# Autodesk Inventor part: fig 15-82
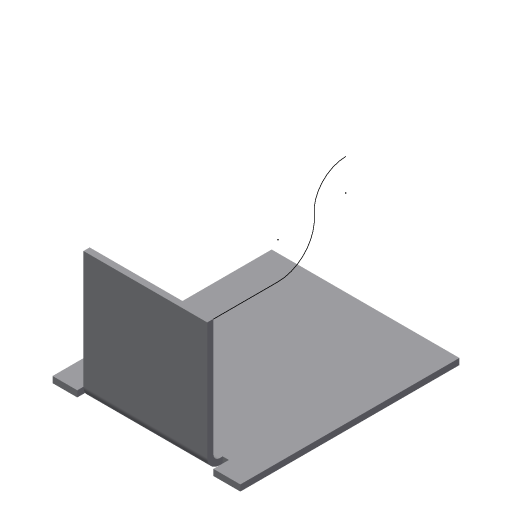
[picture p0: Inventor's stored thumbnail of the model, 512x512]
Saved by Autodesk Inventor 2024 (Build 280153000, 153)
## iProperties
Shininess: 77.0
Angle Display Precision: 2
Document Length Units: 11269
Document Angle Units: 11279
Document Time Units: 11290
Document Mass Units: 11283
Document Length Units Precision: 3
Document Angle Units Precision: 2
Compacted: True
Created: 2002-04
Part Number: fig 15-82
Document SubType Name: Sheet Metal
Density: 1 g/cm^3
Sheet Metal Rule: Default
Material: Generic
Appearance: Default
Density: 0.0
Volumn: 0.0
Area: 0.0
PropertySet Name: Model Information
Control State: 0
Master: False
Checked Out: False
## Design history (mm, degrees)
node "Face1"
  sketch "Sketch1"
    geometry: L1 (-24.824, 17.882)-(5.529, 17.882); L2 (5.529, 17.882)-(5.529, -17.529); L3 (5.529, -17.529)-(-24.824, -17.529); L4 (-24.824, -17.529)-(-24.824, 17.882)
    constraints: 8 end point, 2 parallel, 1 horizontal, 1 perpendicular
node "Flange1"
sketch "Sketch5"
  geometry: L1 (0, 1)-(0, 11.431); A1 r 5.855 centre (-5.855, 11.431) between (0, 11.431) and (-6.422, 17.259); A2 r 5.142 centre (-6.92, 22.376) between (-12.062, 22.382) and (-6.422, 17.259)
  constraints: 4 point on circle, 2 centre point, 2 end point, 2 tangent
body "Solid1"
face "Plate1" dims "d33" = 1 (= Thickness)
sketch "Sketch3"
  geometry: L1 (25.353, 0)-(5.353, 0); L2 (5.353, 0)-(5.353, 20); L3 (5.353, 20)-(25.353, 20); L4 (25.353, 20)-(25.353, 0)
  constraints: 8 end point
face "Plate3" dims "d5" = 20, "d6" = 90 deg, "d7" = 1 (= BendRadius), "d11" = 5, "d12" = 20, "d33" = 1 (= Thickness), "MinimumRemnant" = 2 (= 2 x Thickness), "BendReliefWidth" = 1 (= Thickness)
bend "Bend2" dims "d5" = 20, "d6" = 90 deg, "d7" = 1 (= BendRadius), "d21" = 1 (= BendReliefWidth), "d22" = 0.5 (= BendReliefDepth), "d23" = 2 (= MinimumRemnant), "d33" = 1 (= Thickness), "SeamGap" = 0.01, "MinimumRemnant" = 2 (= 2 x Thickness), "BendReliefWidth" = 1 (= Thickness), "TransitionRadius" = 1 (= BendRadius)
other parameters: "Thickness" = 1, "BendRadius" = 1 (= Thickness), "BendReliefDepth" = 0.5 (= 0.5 x Thickness), "CornerReliefSize" = 4 (= 4 x Thickness), "d0" = 1 (= BendRadius), "d4" = 1 (= BendRadius), "JacobiRadiusSize" = 1 (= Thickness), "GapSize" = 1 (= Thickness)
